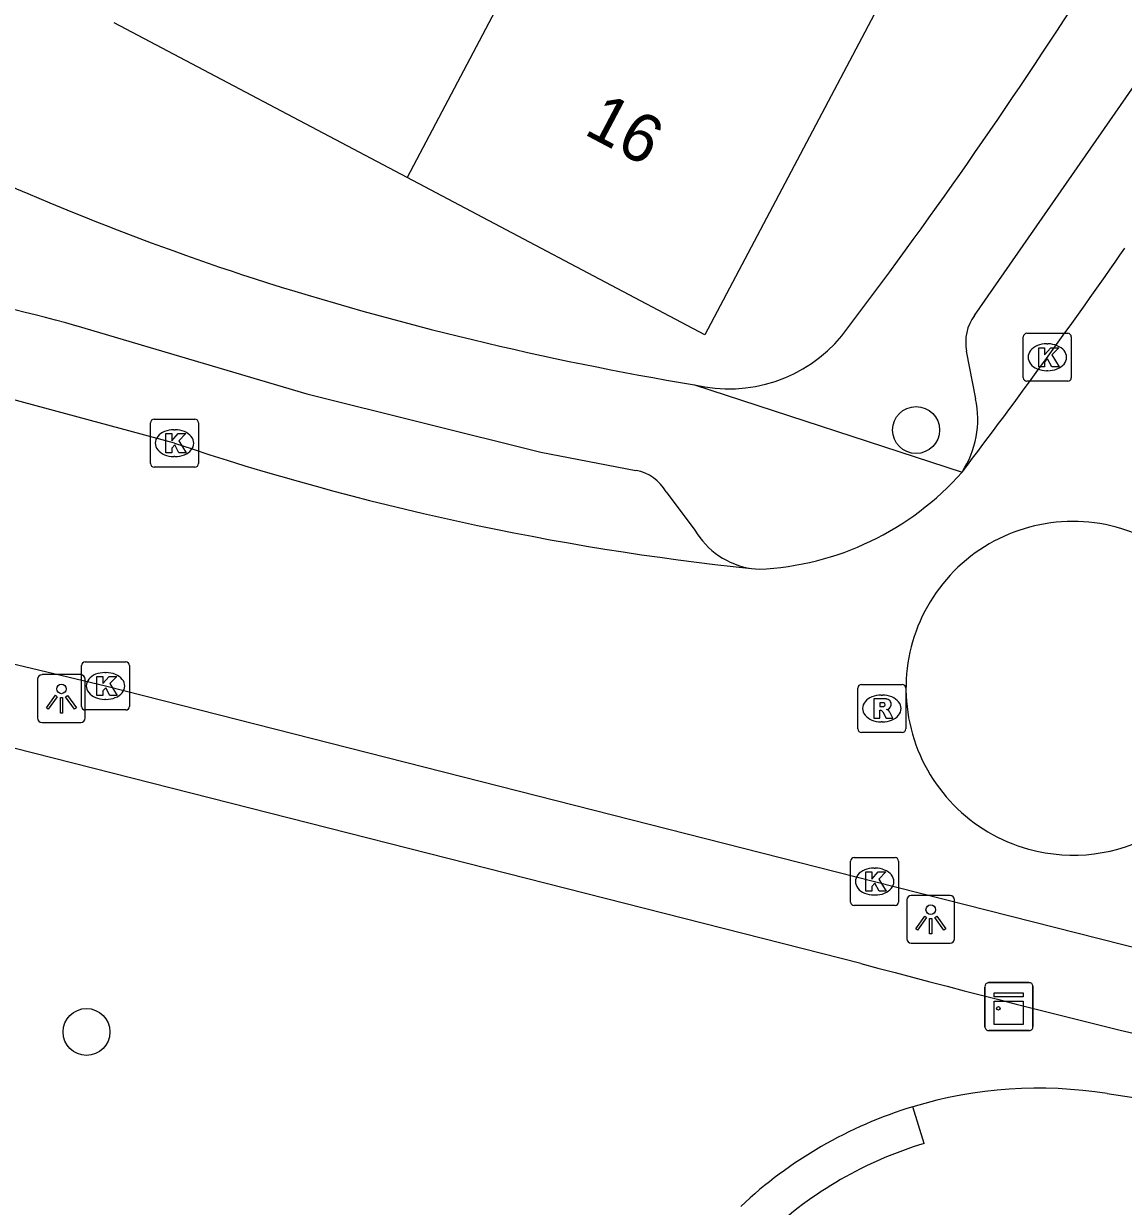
# Model space of a CAD drawing. Extents: x 162675 to 163482, y 379761 to 381227.
# Drawn here: x 163105.59 to 163128.52, y 380890.43 to 380915.09 of the extents above; entities that cross this region are included whole.
import ezdxf

# ---------------------------------------------------------------- set-up
doc = ezdxf.new("R2010")
doc.units = 0
for name, color, linetype in [('IMGEO_Boom', 7, 'Continuous'), ('IMGEO_Groenvoorziening', 7, 'Continuous'), ('IMGEO_Haag', 7, 'Continuous'), ('IMGEO_Kast', 7, 'Continuous'), ('IMGEO_Kolk', 7, 'Continuous'), ('IMGEO_Lichtpunt', 7, 'Continuous'), ('IMGEO_Pand', 7, 'Continuous'), ('IMGEO_Pand_nummerreeks', 7, 'Continuous'), ('IMGEO_Parkeervlak_halfverhard', 7, 'Continuous'), ('IMGEO_Rijbaan_lokaal_open', 7, 'Continuous'), ('IMGEO_Rioolput', 7, 'Continuous'), ('IMGEO_Voetpad_open', 7, 'Continuous')]:
    doc.layers.add(name, color=color, linetype=linetype)

msp = doc.modelspace()

# ---------------------------------------------------------------- linework, layer by layer
at = {"layer": 'IMGEO_Boom'}
for centre in [(163124.197, 380906.618), (163106.897, 380894.069)]:
    msp.add_circle(centre, 0.489, dxfattribs=at)
at = {"layer": 'IMGEO_Groenvoorziening'}
msp.add_lwpolyline([(163128.179, 380892.783), (163132.144, 380892.19)], dxfattribs=at)
msp.add_arc((163126.75, 380883.857), 9.04, 80.9045, 106.8401, dxfattribs=at)
at = {"layer": 'IMGEO_Haag'}
msp.add_lwpolyline([(163124.362, 380891.743), (163124.131, 380892.509)], dxfattribs=at)
for centre, radius, start, end in [((163126.752, 380883.837), 9.059, 106.8182, 133.2749), ((163126.745, 380883.852), 8.243, 106.8003, 133.2066)]:
    msp.add_arc(centre, radius, start, end, dxfattribs=at)
at = {"layer": 'IMGEO_Kast'}
for p, q in [((163125.633, 380894.172), (163125.633, 380895.013)), ((163125.633, 380895.013), (163125.633, 380894.172)), ((163125.708, 380895.097), (163126.549, 380895.097)), ((163126.549, 380895.097), (163125.708, 380895.097)), ((163126.633, 380895.022), (163126.633, 380894.181)), ((163126.633, 380894.181), (163126.633, 380895.022)), ((163126.558, 380894.097), (163125.717, 380894.097)), ((163125.717, 380894.097), (163126.558, 380894.097))]:
    msp.add_line(p, q, dxfattribs=at)
for points in [[(163125.828, 380894.887), (163126.428, 380894.887), (163126.428, 380894.802), (163125.828, 380894.802), (163125.828, 380894.887)], [(163125.828, 380894.712), (163126.428, 380894.712), (163126.428, 380894.223), (163125.828, 380894.223), (163125.828, 380894.712)]]:
    msp.add_lwpolyline(points, dxfattribs=at)
msp.add_circle((163125.912, 380894.561), 0.0377, dxfattribs=at)
for centre, start, end in [((163125.711, 380895.019), 92.4484, 184.2845), ((163125.711, 380895.019), 92.4484, 184.2845), ((163126.555, 380895.019), 2.4484, 94.2845), ((163126.555, 380895.019), 2.4484, 94.2845), ((163126.555, 380894.175), 272.4484, 4.2845), ((163126.555, 380894.175), 272.4484, 4.2845), ((163125.711, 380894.175), 182.4484, 274.2845), ((163125.711, 380894.175), 182.4484, 274.2845)]:
    msp.add_arc(centre, 0.0779, start, end, dxfattribs=at)
at = {"layer": 'IMGEO_Kolk'}
for p, q in [((163126.432, 380907.709), (163126.432, 380908.561)), ((163126.507, 380908.635), (163127.359, 380908.635)), ((163127.433, 380908.561), (163127.433, 380907.709)), ((163126.92, 380908.415), (163126.945, 380908.415)), ((163126.943, 380907.855), (163126.918, 380907.855)), ((163127.359, 380907.635), (163126.507, 380907.635)), ((163108.232, 380905.918), (163108.232, 380906.77)), ((163108.307, 380906.844), (163109.159, 380906.844)), ((163109.233, 380906.77), (163109.233, 380905.918)), ((163108.72, 380906.624), (163108.745, 380906.624)), ((163108.743, 380906.064), (163108.718, 380906.064)), ((163109.159, 380905.844), (163108.307, 380905.844)), ((163106.793, 380900.856), (163106.793, 380901.708)), ((163106.868, 380901.782), (163107.72, 380901.782)), ((163107.794, 380901.708), (163107.794, 380900.856)), ((163107.281, 380901.562), (163107.306, 380901.562)), ((163107.304, 380901.002), (163107.279, 380901.002)), ((163107.72, 380900.782), (163106.868, 380900.782)), ((163122.831, 380896.778), (163122.831, 380897.63)), ((163122.906, 380897.704), (163123.758, 380897.704)), ((163123.832, 380897.63), (163123.832, 380896.778)), ((163123.319, 380897.484), (163123.344, 380897.484)), ((163123.342, 380896.924), (163123.317, 380896.924)), ((163123.758, 380896.704), (163122.906, 380896.704))]:
    msp.add_line(p, q, dxfattribs=at)
for points in [[(163126.432, 380907.709), (163126.432, 380908.561)], [(163126.507, 380908.635), (163127.359, 380908.635)], [(163127.433, 380908.561), (163127.433, 380907.709)], [(163126.753, 380908.335), (163126.876, 380908.335), (163126.876, 380908.184), (163127.006, 380908.335), (163127.17, 380908.335), (163127.024, 380908.184), (163127.177, 380907.935), (163127.025, 380907.935), (163126.94, 380908.099), (163126.876, 380908.032), (163126.876, 380907.935), (163126.753, 380907.935), (163126.753, 380908.335)], [(163127.359, 380907.635), (163126.507, 380907.635)], [(163108.232, 380905.918), (163108.232, 380906.77)], [(163108.307, 380906.844), (163109.159, 380906.844)], [(163109.233, 380906.77), (163109.233, 380905.918)], [(163108.553, 380906.544), (163108.676, 380906.544), (163108.676, 380906.393), (163108.806, 380906.544), (163108.97, 380906.544), (163108.824, 380906.393), (163108.977, 380906.144), (163108.825, 380906.144), (163108.74, 380906.308), (163108.676, 380906.241), (163108.676, 380906.144), (163108.553, 380906.144), (163108.553, 380906.544)], [(163109.159, 380905.844), (163108.307, 380905.844)], [(163106.793, 380900.856), (163106.793, 380901.708)], [(163106.868, 380901.782), (163107.72, 380901.782)], [(163107.794, 380901.708), (163107.794, 380900.856)], [(163107.114, 380901.482), (163107.237, 380901.482), (163107.237, 380901.331), (163107.367, 380901.482), (163107.531, 380901.482), (163107.385, 380901.331), (163107.538, 380901.082), (163107.386, 380901.082), (163107.301, 380901.246), (163107.237, 380901.179), (163107.237, 380901.082), (163107.114, 380901.082), (163107.114, 380901.482)], [(163107.72, 380900.782), (163106.868, 380900.782)], [(163122.831, 380896.778), (163122.831, 380897.63)], [(163122.906, 380897.704), (163123.758, 380897.704)], [(163123.832, 380897.63), (163123.832, 380896.778)], [(163123.152, 380897.404), (163123.275, 380897.404), (163123.275, 380897.253), (163123.405, 380897.404), (163123.569, 380897.404), (163123.423, 380897.253), (163123.576, 380897.004), (163123.424, 380897.004), (163123.339, 380897.168), (163123.275, 380897.101), (163123.275, 380897.004), (163123.152, 380897.004), (163123.152, 380897.404)], [(163123.758, 380896.704), (163122.906, 380896.704)]]:
    msp.add_lwpolyline(points, dxfattribs=at)
for centre, start, end in [((163126.509, 380908.559), 91.552, 178.448), ((163126.509, 380908.559), 91.552, 178.448), ((163127.357, 380908.559), 1.552, 88.448), ((163127.357, 380908.559), 1.552, 88.448), ((163126.509, 380907.711), 181.552, 268.448), ((163126.509, 380907.711), 181.552, 268.448), ((163127.357, 380907.711), 271.552, 358.448), ((163127.357, 380907.711), 271.552, 358.448), ((163108.309, 380906.768), 91.552, 178.448), ((163108.309, 380906.768), 91.552, 178.448), ((163109.157, 380906.768), 1.552, 88.448), ((163109.157, 380906.768), 1.552, 88.448), ((163108.309, 380905.92), 181.552, 268.448), ((163108.309, 380905.92), 181.552, 268.448), ((163109.157, 380905.92), 271.552, 358.448), ((163109.157, 380905.92), 271.552, 358.448), ((163106.87, 380901.706), 91.552, 178.448), ((163106.87, 380901.706), 91.552, 178.448), ((163107.718, 380901.706), 1.552, 88.448), ((163107.718, 380901.706), 1.552, 88.448), ((163106.87, 380900.858), 181.552, 268.448), ((163106.87, 380900.858), 181.552, 268.448), ((163107.718, 380900.858), 271.552, 358.448), ((163107.718, 380900.858), 271.552, 358.448), ((163122.908, 380897.628), 91.552, 178.448), ((163122.908, 380897.628), 91.552, 178.448), ((163123.756, 380897.628), 1.552, 88.448), ((163123.756, 380897.628), 1.552, 88.448), ((163122.908, 380896.78), 181.552, 268.448), ((163122.908, 380896.78), 181.552, 268.448), ((163123.756, 380896.78), 271.552, 358.448), ((163123.756, 380896.78), 271.552, 358.448)]:
    msp.add_arc(centre, 0.0765, start, end, dxfattribs=at)
for centre, major_axis, ratio, start_param, end_param in [((163126.919, 380908.135), (-0.387, 0.002), 0.722429, 4.712389, 7.853982), ((163126.944, 380908.135), (-0.39, 0.002), 0.717154, 1.570796, 4.712389), ((163108.719, 380906.344), (-0.387, 0.002), 0.722429, 4.712389, 7.853982), ((163108.744, 380906.344), (-0.39, 0.002), 0.717154, 1.570796, 4.712389), ((163107.28, 380901.282), (-0.387, 0.002), 0.722429, 4.712389, 7.853982), ((163107.305, 380901.282), (-0.39, 0.002), 0.717154, 1.570796, 4.712389), ((163123.318, 380897.204), (-0.387, 0.002), 0.722429, 4.712389, 7.853982), ((163123.343, 380897.204), (-0.39, 0.002), 0.717154, 1.570796, 4.712389)]:
    msp.add_ellipse(centre, major_axis=major_axis, ratio=ratio, start_param=start_param, end_param=end_param, dxfattribs=at)
at = {"layer": 'IMGEO_Lichtpunt'}
for p, q in [((163105.876, 380901.423), (163105.876, 380900.616)), ((163105.876, 380901.423), (163105.876, 380900.616)), ((163106.778, 380901.518), (163105.97, 380901.518)), ((163106.778, 380901.518), (163105.97, 380901.518)), ((163106.872, 380900.616), (163106.872, 380901.423)), ((163106.872, 380900.616), (163106.872, 380901.423)), ((163105.97, 380900.522), (163106.778, 380900.522)), ((163105.97, 380900.522), (163106.778, 380900.522)), ((163124.905, 380896.915), (163124.097, 380896.915)), ((163124.905, 380896.915), (163124.097, 380896.915)), ((163124.003, 380896.82), (163124.003, 380896.013)), ((163124.003, 380896.82), (163124.003, 380896.013)), ((163124.999, 380896.013), (163124.999, 380896.82)), ((163124.999, 380896.013), (163124.999, 380896.82)), ((163124.097, 380895.919), (163124.905, 380895.919)), ((163124.097, 380895.919), (163124.905, 380895.919))]:
    msp.add_line(p, q, dxfattribs=at)
for points in [[(163106.25, 380901.087), (163106.289, 380901.059), (163106.101, 380900.797), (163106.063, 380900.824), (163106.25, 380901.087)], [(163106.462, 380901.059), (163106.5, 380901.086), (163106.687, 380900.824), (163106.648, 380900.796), (163106.462, 380901.059)], [(163106.352, 380901.039), (163106.399, 380901.039), (163106.399, 380900.717), (163106.352, 380900.717), (163106.352, 380901.039)], [(163124.377, 380896.484), (163124.416, 380896.456), (163124.228, 380896.194), (163124.19, 380896.221), (163124.377, 380896.484)], [(163124.479, 380896.436), (163124.526, 380896.436), (163124.526, 380896.114), (163124.479, 380896.114), (163124.479, 380896.436)], [(163124.589, 380896.456), (163124.627, 380896.483), (163124.814, 380896.221), (163124.775, 380896.193), (163124.589, 380896.456)]]:
    msp.add_lwpolyline(points, dxfattribs=at)
for centre in [(163106.375, 380901.221), (163124.502, 380896.618)]:
    msp.add_circle(centre, 0.0994, dxfattribs=at)
for centre, start, end in [((163105.97, 380901.423), 90, 180), ((163105.97, 380901.423), 90, 180), ((163106.778, 380901.423), 0, 90), ((163106.778, 380901.423), 0, 90), ((163105.97, 380900.616), 180, 270), ((163105.97, 380900.616), 180, 270), ((163106.778, 380900.616), 270, 0), ((163106.778, 380900.616), 270, 360), ((163124.097, 380896.82), 90, 180), ((163124.097, 380896.82), 90, 180), ((163124.905, 380896.82), 0, 90), ((163124.905, 380896.82), 0, 90), ((163124.097, 380896.013), 180, 270), ((163124.097, 380896.013), 180, 270), ((163124.905, 380896.013), 270, 0), ((163124.905, 380896.013), 270, 360)]:
    msp.add_arc(centre, 0.0946, start, end, dxfattribs=at)
at = {"layer": 'IMGEO_Pand'}
for points in [[(163117.783, 380919.841), (163122.278, 380917.471), (163123.721, 380920.21), (163125.444, 380919.301), (163119.792, 380908.606), (163113.582, 380911.885)], [(163117.783, 380919.841), (163117.704, 380919.692), (163113.582, 380911.885)], [(163113.582, 380911.885), (163107.478, 380915.107)]]:
    msp.add_lwpolyline(points, dxfattribs=at)
at = {"layer": 'IMGEO_Parkeervlak_halfverhard'}
msp.add_lwpolyline([(163123.041, 380895.496), (163102.916, 380900.611)], dxfattribs=at)
msp.add_arc((163194.221, 381161.87), 275.72, 255.03912, 257.51575, dxfattribs=at)
at = {"layer": 'IMGEO_Rijbaan_lokaal_open'}
for points in [[(163108.733, 380906.344), (163104.892, 380907.377)], [(163120.765, 380903.73), (163120.845, 380903.722), (163120.924, 380903.714)], [(163103.586, 380902.166), (163107.294, 380901.282), (163123.332, 380897.204), (163129.44, 380895.655), (163134.958, 380894.385)]]:
    msp.add_lwpolyline(points, dxfattribs=at)
for centre, radius, start, end in [((163014.881, 380989.462), 138.455, 322.79452, 325.18429), ((163126.701, 380960.053), 56.635, 251.5023, 263.9832), ((163120.637, 380909.745), 6.038, 272.7252, 318.4723), ((163127.464, 380901.235), 3.478, 72.934, 254.6524), ((163127.474, 380901.232), 3.477, 254.4911, 73.0953)]:
    msp.add_arc(centre, radius, start, end, dxfattribs=at)
at = {"layer": 'IMGEO_Rioolput'}
for p, q in [((163122.981, 380900.387), (163122.981, 380901.239)), ((163123.056, 380901.313), (163123.908, 380901.313)), ((163123.469, 380901.093), (163123.494, 380901.093)), ((163123.982, 380901.239), (163123.982, 380900.387)), ((163123.492, 380900.533), (163123.467, 380900.533)), ((163123.908, 380900.313), (163123.056, 380900.313))]:
    msp.add_line(p, q, dxfattribs=at)
for points in [[(163122.981, 380900.387), (163122.981, 380901.239)], [(163123.056, 380901.313), (163123.908, 380901.313)], [(163123.982, 380901.239), (163123.982, 380900.387)], [(163123.57, 380901.011), (163123.318, 380901.013), (163123.318, 380900.613)], [(163123.496, 380900.932), (163123.442, 380900.932), (163123.442, 380900.851)], [(163123.442, 380900.851), (163123.494, 380900.851)], [(163123.318, 380900.613), (163123.442, 380900.613), (163123.442, 380900.775), (163123.453, 380900.775)], [(163123.5, 380900.746), (163123.571, 380900.613), (163123.711, 380900.613), (163123.646, 380900.739)], [(163123.908, 380900.313), (163123.056, 380900.313)]]:
    msp.add_lwpolyline(points, dxfattribs=at)
for centre, radius, start, end in [((163123.058, 380901.237), 0.0765, 91.552, 178.448), ((163123.058, 380901.237), 0.0765, 91.552, 178.448), ((163123.906, 380901.237), 0.0765, 1.552, 88.448), ((163123.906, 380901.237), 0.0765, 1.552, 88.448), ((163123.478, 380901.04), 0.19, 274.7715, 282.9687), ((163123.502, 380900.836), 0.0964, 77.0061, 93.1865), ((163123.516, 380900.893), 0.0378, 276.6634, 79.6772), ((163123.569, 380900.901), 0.109, 350.3612, 89.416), ((163123.567, 380900.901), 0.112, 277.5842, 350.9817), ((163123.452, 380900.722), 0.0533, 26.0293, 88.6989), ((163123.551, 380900.686), 0.108, 29.5134, 73.7905), ((163123.058, 380900.389), 0.0765, 181.552, 268.448), ((163123.058, 380900.389), 0.0765, 181.552, 268.448), ((163123.906, 380900.389), 0.0765, 271.552, 358.448), ((163123.906, 380900.389), 0.0765, 271.552, 358.448)]:
    msp.add_arc(centre, radius, start, end, dxfattribs=at)
for centre, major_axis, ratio, start_param, end_param in [((163123.468, 380900.813), (-0.387, 0.002), 0.722429, 4.712389, 7.853982), ((163123.493, 380900.813), (-0.39, 0.002), 0.717154, 1.570796, 4.712389)]:
    msp.add_ellipse(centre, major_axis=major_axis, ratio=ratio, start_param=start_param, end_param=end_param, dxfattribs=at)
at = {"layer": 'IMGEO_Voetpad_open'}
for points in [[(163125.413, 380909.007), (163128.856, 380913.957)], [(163106.676, 380908.794), (163111.492, 380907.375), (163116.37, 380906.157), (163118.356, 380905.771)], [(163125.439, 380907.267), (163125.25, 380908.261)], [(163119.578, 380907.561), (163125.157, 380905.742)], [(163118.983, 380905.328), (163119.582, 380904.533)]]:
    msp.add_lwpolyline(points, dxfattribs=at)
for centre, radius, start, end in [((163128.458, 380965.083), 58.182, 236.02455, 251.90986), ((163033.545, 380976.237), 111.878, 322.7904, 327.34487), ((163093.951, 380862.34), 48.165, 74.6811, 83.0168), ((163130.382, 380972.495), 65.827, 252.32133, 260.55325), ((163126.179, 380908.449), 0.948, 143.9144, 191.4349), ((163120.296, 380910.529), 3.054, 256.3935, 320.3644), ((163123.462, 380906.844), 2.021, 326.9656, 12.0811), ((163118.222, 380904.916), 0.866, 28.4383, 81.0763), ((163121.018, 380905.376), 1.665, 210.4053, 261.2588)]:
    msp.add_arc(centre, radius, start, end, dxfattribs=at)

# ---------------------------------------------------------------- texts
at = {"layer": 'IMGEO_Pand_nummerreeks'}
msp.add_text('16', height=1, rotation=332.1692, dxfattribs=at).set_placement((163117.244, 380912.8))

doc.saveas('drawing.dxf')
